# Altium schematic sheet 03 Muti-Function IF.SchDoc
size 299 x 210 mm
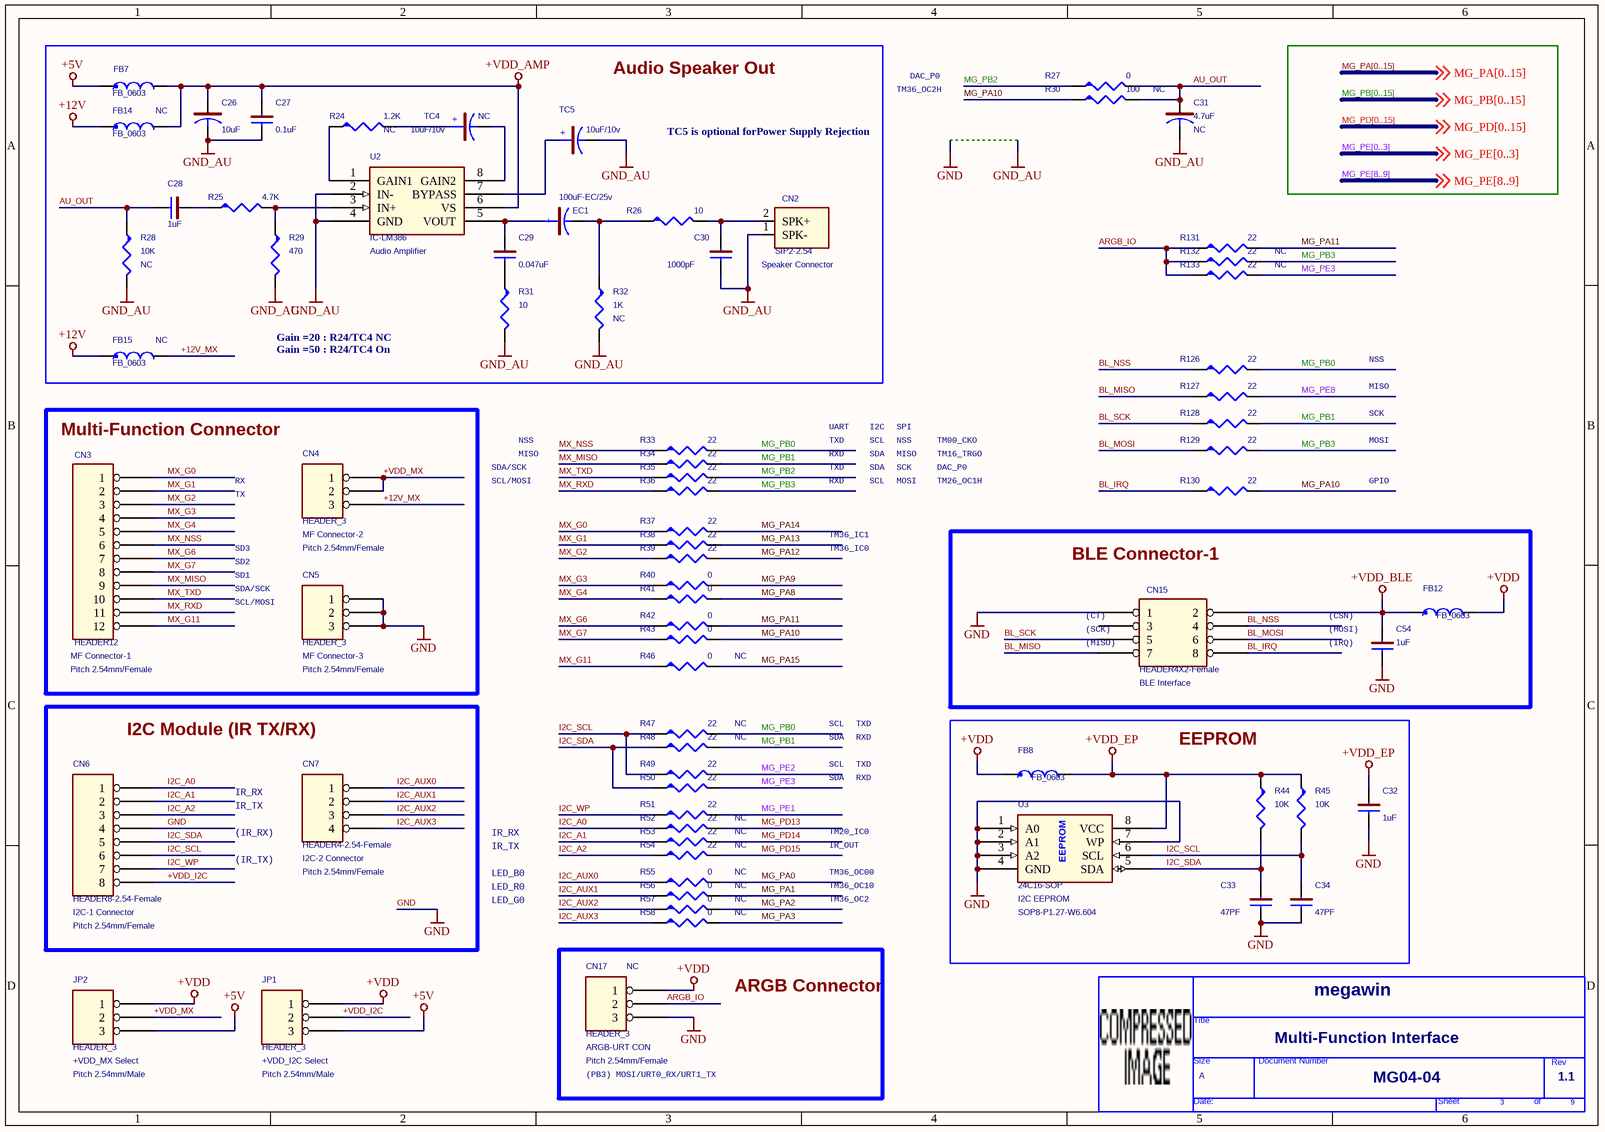
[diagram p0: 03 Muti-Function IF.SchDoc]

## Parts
*  OrgName: megawin  Doc: MG04-04  RevCode: 1.1  Title: Multi-Function Interface  Page Size: A  Page Number: 3  Page Count: 9  (hidden comment: TitleBlock_MegaWin)  (graphical)
C26  10uF  [C-0805]
C27  0.1uF  [C-0603]
C28  1uF  [C-0603]
C29  0.047uF  [C-0603]
C30  1000pF  [C-0603]
C31  4.7uF  Assembly: NC  [C-0805]
C32  1uF  [C-0603]
C33  47PF  [C-0603]
C34  47PF  [C-0603]
C54  1uF  [C-0603]
CN2  SIP2-2.54  Function: Speaker Connector  [SIP2-2.54]
CN3  HEADER12  Package: Pitch 2.54mm/Female  Function: MF Connector-1  [SIP12-P2.54]
CN4  HEADER_3  Package: Pitch 2.54mm/Female  Function: MF Connector-2  [SIP3-P2.54]
CN5  HEADER_3  Package: Pitch 2.54mm/Female  Function: MF Connector-3  [SIP3-P2.54]
CN6  HEADER8-2.54-Female  Package: Pitch 2.54mm/Female  Function: I2C-1 Connector  [SIP8-P2.54]
CN7  HEADER4-2.54-Female  Package: Pitch 2.54mm/Female  Function: I2C-2 Connector  [SIP4-P2.54]
CN15  HEADER4X2-Female  Function: BLE Interface  [HD4X2-P2.54]
CN17  HEADER_3  Package: Pitch 2.54mm/Female  Assembly: NC  Function: ARGB-URT CON  [SIP3-P2.54]
EC1  100uF-EC/25v  [C-EC-S-P7.2-T6.3X5.5]
FB7  FB_0603  [L-0603]
FB8  FB_0603  [L-0603]
FB12  FB_0603  [L-0603]
FB14  FB_0603  Assembly: NC  [L-0603]
FB15  FB_0603  Assembly: NC  [L-0603]
JP1  HEADER_3  Function: +VDD_I2C Select  Package: Pitch 2.54mm/Male  [SIP3-P2.54]
JP2  HEADER_3  Function: +VDD_MX Select  Package: Pitch 2.54mm/Male  [SIP3-P2.54]
R24  1.2K  Assembly: NC  [R-0603]
R25  4.7K  [R-0603]
R26  10  [R-0603]
R27  0  [R-0603]
R28  10K  Assembly: NC  [R-0603]
R29  470  [R-0603]
R30  100  Assembly: NC  [R-0603]
R31  10  [R-0603]
R32  1K  Assembly: NC  [R-0603]
R33  22  [R-0603]
R34  22  [R-0603]
R35  22  [R-0603]
R36  22  [R-0603]
R37  22  [R-0603]
R38  22  [R-0603]
R39  22  [R-0603]
R40  0  [R-0603]
R41  0  [R-0603]
R42  0  [R-0603]
R43  0  [R-0603]
R44  10K  [R-0603]
R45  10K  [R-0603]
R46  0  Assembly: NC  [R-0603]
R47  22  Assembly: NC  [R-0603]
R48  22  Assembly: NC  [R-0603]
R49  22  [R-0603]
R50  22  [R-0603]
R51  22  [R-0603]
R52  22  Assembly: NC  [R-0603]
R53  22  Assembly: NC  [R-0603]
R54  22  Assembly: NC  [R-0603]
R55  0  Assembly: NC  [R-0603]
R56  0  Assembly: NC  [R-0603]
R57  0  Assembly: NC  [R-0603]
R58  0  Assembly: NC  [R-0603]
R126  22  [R-0603]
R127  22  [R-0603]
R128  22  [R-0603]
R129  22  [R-0603]
R130  22  [R-0603]
R131  22  [R-0603]
R132  22  Assembly: NC  [R-0603]
R133  22  Assembly: NC  [R-0603]
TC4  10uF/10v  Assembly: NC  [C-1210+]
TC5  10uF/10v  [C-1210+]
U2  IC-LM386  Function: Audio Amplifier  [SOP8-P1.27-W6.2]
U3  24C16-SOP  Function: I2C EEPROM  [SOP8-P1.27-W6.604]

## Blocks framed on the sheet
Audio Speaker Out: C26-C30 CN2 EC1 FB7 FB14 FB15 R24-R26 R28 R29 R31 R32 TC4 TC5 U2
Multi-Function Connector: CN3-CN5
BLE Connector-1: C54 CN15 FB12
I2C Module (IR TX/RX): CN6 CN7
EEPROM: C32-C34 FB8 R44 R45 U3
ARGB / Connector: CN17

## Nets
+5V: FB7.1 JP1.3 JP2.3
+12V: FB14.1 FB15.1
+VDD: CN17.1 FB8.1 FB12.2 JP1.1 JP2.1
+VDD_AMP: C26.1 C27.1 FB7.2 FB14.2 U2.6(VS)
+VDD_BLE: C54.1 CN15.2 FB12.1
+VDD_EP: C32.1 FB8.2 R44.1 R45.1 U3.8(VCC)
GND: C32.2 C33.2 C34.2 C54.2 CN5.1 CN5.2 CN5.3 CN6.4 CN15.1 CN17.3 U3.1(A0) U3.2(A1) U3.3(A2) U3.4(GND) U3.7(WP)
GND_AU: C26.2 C27.2 C30.2 C31.2 CN2.1(SPK-) R28.2 R29.2 R31.2 R32.2 TC5.2 U2.2(IN-) U2.4(GND)
+12V_MX: CN4.3 FB15.2
+VDD_I2C: CN6.8 JP1.2
+VDD_MX: CN4.1 CN4.2 JP2.2
ARGB_IO: CN17.2 R131.1 R132.1 R133.1
AU_OUT: C28.2 C31.1 R27.2 R28.1 R30.2
BL_IRQ: CN15.8 R130.1
BL_MISO: CN15.7 R127.1
BL_MOSI: CN15.6 R129.1
BL_NSS: CN15.4 R126.1
BL_SCK: CN15.5 R128.1
I2C_A0: CN6.1 R52.1
I2C_A1: CN6.2 R53.1
I2C_A2: CN6.3 R54.1
I2C_AUX0: CN7.1 R55.1
I2C_AUX1: CN7.2 R56.1
I2C_AUX2: CN7.3 R57.1
I2C_AUX3: CN7.4 R58.1
I2C_SCL: C34.1 CN6.6 R45.2 R47.1 R49.1 U3.6(SCL)
I2C_SDA: C33.1 CN6.5 R44.2 R48.1 R50.1 U3.5(SDA)
I2C_WP: CN6.7 R51.1
MG_PA0: R55.2
MG_PA1: R56.2
MG_PA2: R57.2
MG_PA3: R58.2
MG_PA8: R41.2
MG_PA9: R40.2
MG_PA10: R30.1 R43.2 R130.2
MG_PA11: R42.2 R131.2
MG_PA12: R39.2
MG_PA13: R38.2
MG_PA14: R37.2
MG_PA15: R46.2
MG_PB0: R33.2 R47.2 R126.2
MG_PB1: R34.2 R48.2 R128.2
MG_PB2: R27.1 R35.2
MG_PB3: R36.2 R129.2 R132.2
MG_PD13: R52.2
MG_PD14: R53.2
MG_PD15: R54.2
MG_PE1: R51.2
MG_PE2: R49.2
MG_PE3: R50.2 R133.2
MG_PE8: R127.2
MX_G0: CN3.1 R37.1
MX_G1: CN3.2 R38.1
MX_G2: CN3.3 R39.1
MX_G3: CN3.4 R40.1
MX_G4: CN3.5 R41.1
MX_G6: CN3.7 R42.1
MX_G7: CN3.8 R43.1
MX_G11: CN3.12 R46.1
MX_MISO: CN3.9 R34.1
MX_NSS: CN3.6 R33.1
MX_RXD: CN3.11 R36.1
MX_TXD: CN3.10 R35.1
NetC28_1: C28.1 R25.1
NetC29_1: C29.1 EC1.1 U2.5(VOUT)
NetC29_2: C29.2 R31.1
NetC30_1: C30.1 CN2.2(SPK+) R26.2
NetEC1_2: EC1.2 R26.1 R32.1
NetR24_1: R24.1 U2.1(GAIN1)
NetR24_2: R24.2 TC4.1
NetR25_2: R25.2 R29.1 U2.3(IN+)
NetTC4_2: TC4.2 U2.8(GAIN2)
NetTC5_1: TC5.1 U2.7(BYPASS)

Not connected (* = marked no-connect by the designer): CN15 3

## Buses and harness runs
bus MG_PA[0..15]
bus MG_PB[0..15]
bus MG_PD[0..15]
bus MG_PE[0..3]
bus MG_PE[8..9]

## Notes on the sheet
- TC5 is optional forPower Supply Rejection
- TM36_OC2H
- DAC_P0
- Gain =20 : R24/TC4 NC
  Gain =50 : R24/TC4 On
- MISO
- NSS
- SDA/SCK
- TXD
- RXD
- UART
- SCL
- SDA
- I2C
- SCK
- SPI
- TM16_TRGO
- TM00_CKO
- MOSI
- RX
- TX
- SCL/MOSI
- TM36_IC1
- TM26_OC1H
- GPIO
- SD3
- SD2
- SD1
- TM36_IC0
- (near CN15) (MISO)
- (near CN15) (CT)
- (near CN15) (SCK)
- (near C54) (MOSI)
- (near C54) (IRQ)
- (near C54) (CSN)
- IR_RX
- IR_TX
- (IR_TX)
- (IR_RX)
- LED_B0
- TM36_OC00
- IR_OUT
- TM20_IC0
- LED_R0
- LED_G0
- TM36_OC10
- TM36_OC2
- (PB3) MOSI/URT0_RX/URT1_TX

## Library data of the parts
C26 C31 = CAP-POL
C27-C30 C33 C34 C54 = CAP-NP
C32 = CAP-NP: 2ND PART FIELD: SMD_0805
CN2 = SIP2-SPK
CN4 CN5 CN17 JP1 JP2 = HEADER3: 2ND PART FIELD: Pitch 2.54mm
CN6 = HEADER8
CN7 = HEADER4
CN15 = HEADER4X2
EC1 TC4 TC5 = CAP +
FB7 FB8 FB12 FB14 FB15 = FB2
R24 R25 R28 R29 R31 R32 = R
R26 R27 R30 = R: 2ND PART FIELD: SMD_1
R33-R58 R126-R133 = R: 2ND PART FIELD: SMD_0805
U3 = ICM-24CXX: 1ST PART FIELD: OSD Record Buffer; 2ND PART FIELD: SOP_8PIN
